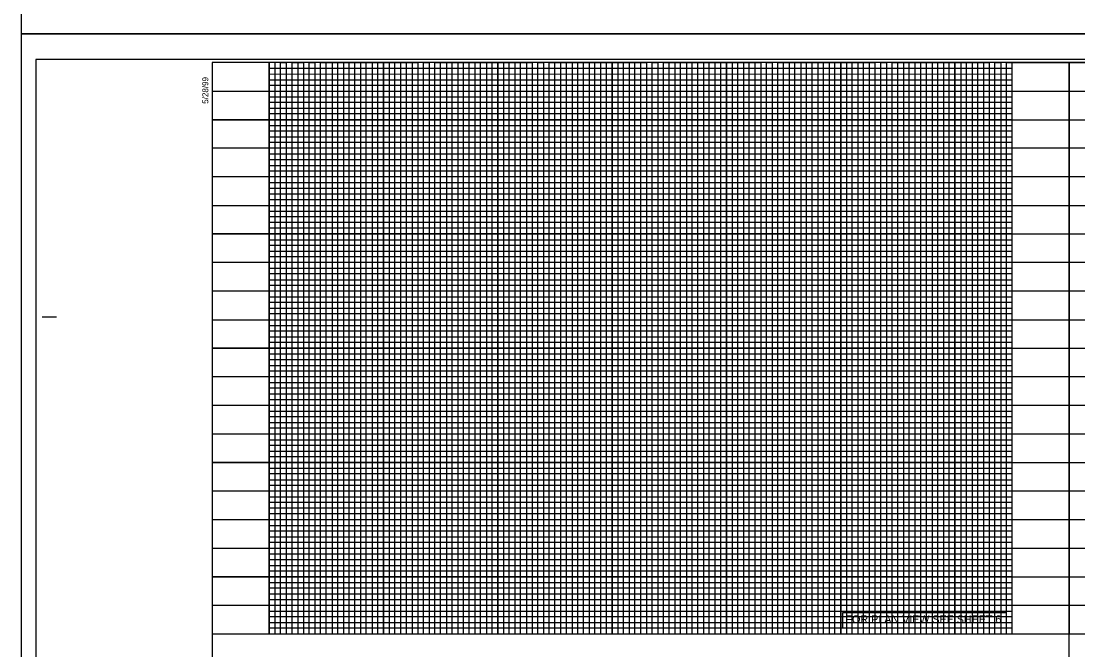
# Model space of a CAD drawing. Extents: x 1755181 to 1757273, y 729911 to 735411.
# Drawn here: x 1755181 to 1756105, y 730472 to 731022 of the extents above; entities that cross this region are included whole.
import ezdxf

# ---------------------------------------------------------------- set-up
doc = ezdxf.new("R2010")
doc.units = 0
for name, color, linetype in [('Prop Grid Mask', 7, 'Continuous'), ('Prop VPI Label', 7, 'Continuous'), ('Scratch_Level_3', 7, 'Continuous'), ('Sheet Cutting Line CELL', 7, 'Continuous'), ('Sheet DOT Grid CELL', 7, 'Continuous'), ('Sheet Plot Border Inside CELL', 7, 'Continuous'), ('Sheet Plot Border Outside CELL', 7, 'Continuous'), ('Sheet Profile CELL', 7, 'Continuous'), ('Sheet Profile Grid Major CELL', 7, 'Continuous'), ('Sheet Profile Grid Middle CELL', 7, 'Continuous'), ('Sheet Profile Grid Minor CELL', 7, 'Continuous')]:
    doc.layers.add(name, color=color, linetype=linetype)

msp = doc.modelspace()

# ---------------------------------------------------------------- linework, layer by layer
at = {"layer": 'Prop Grid Mask'}
msp.add_lwpolyline([(1755899.57, 730504.63), (1756042.57, 730504.63), (1756042.57, 730490.9), (1755899.57, 730490.9)], close=True, dxfattribs=at)
at = {"layer": 'Scratch_Level_3'}
for points in [[(1755347.67, 730460.78), (1756097.67, 730460.78), (1756097.67, 730985.78), (1755347.67, 730985.78)], [(1756097.67, 730460.78), (1756097.67, 730985.78), (1756647.63, 730985.78), (1756647.63, 730752.66), (1756847.68, 730752.66), (1756847.68, 730460.78)]]:
    msp.add_lwpolyline(points, close=True, dxfattribs=at)
at = {"layer": 'Sheet Cutting Line CELL'}
for p, q in [((1755180.67, 732110.78), (1755180.67, 731010.78)), ((1755180.67, 731010.78), (1756864.67, 731010.78)), ((1755180.67, 731010.78), (1755180.67, 729910.78))]:
    msp.add_line(p, q, dxfattribs=at)
at = {"layer": 'Sheet DOT Grid CELL'}
for p, q in [((1755397.67, 730485.78), (1755397.67, 730985.78)), ((1755447.67, 730485.78), (1755447.67, 730985.78)), ((1755497.67, 730485.78), (1755497.67, 730985.78)), ((1755547.67, 730485.78), (1755547.67, 730985.78)), ((1755597.67, 730485.78), (1755597.67, 730985.78)), ((1755647.67, 730485.78), (1755647.67, 730985.78)), ((1755697.67, 730485.78), (1755697.67, 730985.78)), ((1755747.67, 730485.78), (1755747.67, 730985.78)), ((1755797.67, 730485.78), (1755797.67, 730985.78)), ((1755847.67, 730485.78), (1755847.67, 730985.78)), ((1755897.67, 730485.78), (1755897.67, 730985.78)), ((1755947.67, 730485.78), (1755947.67, 730985.78)), ((1755997.67, 730485.78), (1755997.67, 730985.78)), ((1756047.67, 730485.78), (1756047.67, 730985.78)), ((1756097.67, 730485.78), (1756097.67, 730985.78)), ((1756047.68, 730935.78), (1755347.67, 730935.78)), ((1756047.68, 730885.78), (1755347.67, 730885.78)), ((1756047.68, 730835.78), (1755347.67, 730835.78)), ((1756047.68, 730785.78), (1755347.67, 730785.78)), ((1756047.68, 730735.78), (1755347.67, 730735.78)), ((1756047.68, 730685.78), (1755347.67, 730685.78)), ((1756047.68, 730635.78), (1755347.67, 730635.78)), ((1756047.68, 730585.78), (1755347.67, 730585.78)), ((1756047.68, 730535.78), (1755347.67, 730535.78))]:
    msp.add_line(p, q, dxfattribs=at)
at = {"layer": 'Sheet Plot Border Inside CELL'}
msp.add_lwpolyline([(1755193.67, 729933.23), (1756860.17, 729933.23), (1756860.17, 730988.33), (1755193.67, 730988.33)], close=True, dxfattribs=at)
at = {"layer": 'Sheet Plot Border Outside CELL'}
for points in [[(1755180.67, 731010.78), (1756864.67, 731010.78), (1756864.67, 732110.78), (1755180.67, 732110.78)], [(1755180.67, 729910.78), (1756864.67, 729910.78), (1756864.67, 731010.78), (1755180.67, 731010.78)]]:
    msp.add_lwpolyline(points, close=True, dxfattribs=at)
at = {"layer": 'Sheet Profile CELL'}
for p, q in [((1756097.67, 730985.78), (1756097.67, 730485.78)), ((1755199.17, 730763.28), (1755211.67, 730763.28)), ((1755347.67, 730485.78), (1756847.67, 730485.78))]:
    msp.add_line(p, q, dxfattribs=at)
msp.add_lwpolyline([(1756847.67, 730985.78), (1755347.67, 730985.78), (1755347.67, 729935.78), (1756847.67, 729935.78)], close=True, dxfattribs=at)
at = {"layer": 'Sheet Profile Grid Major CELL'}
for points in [[(1755397.67, 730985.78), (1755397.67, 730485.78), (1755447.67, 730485.78), (1755447.67, 730985.78), (1755497.67, 730985.78), (1755497.67, 730485.78), (1755547.67, 730485.78), (1755547.67, 730985.78), (1755597.67, 730985.78), (1755597.67, 730485.78), (1755647.67, 730485.78), (1755647.67, 730985.78), (1755697.67, 730985.78), (1755697.67, 730485.78), (1755747.67, 730485.78), (1755747.67, 730985.78), (1755797.67, 730985.78), (1755797.67, 730485.78), (1755847.67, 730485.78), (1755847.67, 730985.78), (1755897.67, 730985.78), (1755897.67, 730485.78), (1755947.67, 730485.78), (1755947.67, 730985.78), (1755997.67, 730985.78), (1755997.67, 730485.78), (1756047.67, 730485.78), (1756047.67, 730985.78), (1756097.67, 730985.78), (1756097.67, 730485.78), (1756147.67, 730485.78)], [(1755347.67, 730935.78), (1756647.67, 730935.78)], [(1756647.67, 730885.78), (1755347.67, 730885.78), (1755347.67, 730835.78), (1756647.67, 730835.78)], [(1756647.63, 730785.78), (1755347.67, 730785.78), (1755347.67, 730735.78), (1756847.67, 730735.78)], [(1756847.67, 730685.78), (1755347.67, 730685.78), (1755347.67, 730635.78), (1756847.67, 730635.78)], [(1756847.67, 730585.78), (1755347.67, 730585.78), (1755347.67, 730585.78), (1755347.67, 730535.78), (1756847.67, 730535.78)]]:
    msp.add_lwpolyline(points, dxfattribs=at)
at = {"layer": 'Sheet Profile Grid Middle CELL'}
for p, q in [((1755422.67, 730985.78), (1755422.67, 730485.78)), ((1755472.67, 730485.78), (1755472.67, 730985.78)), ((1755472.67, 730985.78), (1755522.67, 730985.78)), ((1755522.67, 730985.78), (1755522.67, 730485.78)), ((1755572.67, 730485.78), (1755572.67, 730985.78)), ((1755572.67, 730985.78), (1755622.67, 730985.78)), ((1755622.67, 730985.78), (1755622.67, 730485.78)), ((1755672.67, 730485.78), (1755672.67, 730985.78)), ((1755672.67, 730985.78), (1755722.67, 730985.78)), ((1755722.67, 730985.78), (1755722.67, 730485.78)), ((1755772.67, 730485.78), (1755772.67, 730985.78)), ((1755772.67, 730985.78), (1755822.67, 730985.78)), ((1755822.67, 730985.78), (1755822.67, 730485.78)), ((1755872.67, 730485.78), (1755872.67, 730985.78)), ((1755872.67, 730985.78), (1755922.67, 730985.78)), ((1755922.67, 730985.78), (1755922.67, 730485.78)), ((1755972.67, 730485.78), (1755972.67, 730985.78)), ((1755972.67, 730985.78), (1756022.67, 730985.78)), ((1756022.67, 730985.78), (1756022.67, 730485.78)), ((1756072.67, 730985.78), (1756122.67, 730985.78)), ((1755347.67, 730960.78), (1756647.62, 730960.78)), ((1755422.67, 730485.78), (1755472.67, 730485.78)), ((1755522.67, 730485.78), (1755572.67, 730485.78)), ((1755622.67, 730485.78), (1755672.67, 730485.78)), ((1755722.67, 730485.78), (1755772.67, 730485.78)), ((1755822.67, 730485.78), (1755872.67, 730485.78)), ((1755922.67, 730485.78), (1755972.67, 730485.78)), ((1755972.67, 730485.78), (1755972.67, 730485.78)), ((1756022.67, 730485.78), (1756072.67, 730485.78))]:
    msp.add_line(p, q, dxfattribs=at)
for points in [[(1756647.67, 730910.78), (1755347.67, 730910.78), (1755347.67, 730860.78), (1756647.67, 730860.78)], [(1756647.62, 730810.78), (1755347.67, 730810.78), (1755347.67, 730760.78), (1756647.63, 730760.78)], [(1756847.67, 730710.78), (1755347.67, 730710.78), (1755347.67, 730660.78), (1756847.67, 730660.78)], [(1756847.67, 730610.78), (1755347.67, 730610.78), (1755347.67, 730560.78), (1756847.67, 730560.78)], [(1756847.67, 730510.78), (1755347.67, 730510.78)]]:
    msp.add_lwpolyline(points, dxfattribs=at)
at = {"layer": 'Sheet Profile Grid Minor CELL'}
for p, q in [((1755927.67, 730985.78), (1755927.67, 730485.78)), ((1755932.67, 730485.78), (1755932.67, 730985.78)), ((1755932.67, 730985.78), (1755937.67, 730985.78)), ((1755937.67, 730985.78), (1755937.67, 730485.78)), ((1755942.67, 730485.78), (1755942.67, 730985.78)), ((1755942.67, 730985.78), (1755952.67, 730985.78)), ((1755952.67, 730985.78), (1755952.67, 730485.78)), ((1755957.67, 730485.78), (1755957.67, 730985.78)), ((1755957.67, 730985.78), (1755962.67, 730985.78)), ((1755962.67, 730985.78), (1755962.67, 730485.78)), ((1755967.67, 730485.78), (1755967.67, 730985.78)), ((1755967.67, 730985.78), (1755977.67, 730985.78)), ((1755977.67, 730985.78), (1755977.67, 730485.78)), ((1755982.67, 730485.78), (1755982.67, 730985.78)), ((1755982.67, 730985.78), (1755987.67, 730985.78)), ((1755987.67, 730985.78), (1755987.67, 730485.78)), ((1755992.67, 730485.78), (1755992.67, 730985.78)), ((1755992.67, 730985.78), (1756002.67, 730985.78)), ((1756002.67, 730985.78), (1756002.67, 730485.78)), ((1756007.67, 730485.78), (1756007.67, 730985.78)), ((1756007.67, 730985.78), (1756012.67, 730985.78)), ((1756012.67, 730985.78), (1756012.67, 730485.78)), ((1756017.67, 730485.78), (1756017.67, 730985.78)), ((1756017.67, 730985.78), (1756027.67, 730985.78)), ((1756027.67, 730985.78), (1756027.67, 730485.78)), ((1756032.67, 730485.78), (1756032.67, 730985.78)), ((1756032.67, 730985.78), (1756037.67, 730985.78)), ((1756037.67, 730985.78), (1756037.67, 730485.78)), ((1756042.67, 730485.78), (1756042.67, 730985.78)), ((1756042.67, 730985.78), (1756052.67, 730985.78)), ((1756057.67, 730985.78), (1756062.67, 730985.78)), ((1756067.67, 730985.78), (1756077.67, 730985.78)), ((1756082.67, 730985.78), (1756087.67, 730985.78)), ((1756092.67, 730985.78), (1756102.67, 730985.78)), ((1755397.67, 730980.78), (1756047.68, 730980.78)), ((1755397.67, 730975.78), (1755397.67, 730975.78)), ((1756047.68, 730975.62), (1755397.67, 730975.43)), ((1755397.67, 730970.78), (1756047.68, 730970.78)), ((1756047.68, 730850.78), (1755397.67, 730850.78)), ((1756047.68, 730845.78), (1755397.67, 730845.78)), ((1756047.68, 730840.78), (1755397.67, 730840.78)), ((1755397.67, 730830.78), (1756047.68, 730830.78)), ((1756047.68, 730825.78), (1755397.67, 730825.78)), ((1755397.67, 730820.78), (1756047.68, 730820.78)), ((1756047.68, 730800.78), (1755397.67, 730800.78)), ((1755397.67, 730795.78), (1756047.68, 730795.78)), ((1756047.68, 730775.78), (1755397.67, 730775.78)), ((1755397.67, 730770.78), (1756047.68, 730770.78)), ((1756047.68, 730750.78), (1755397.67, 730750.78)), ((1755397.67, 730745.78), (1756047.68, 730745.78)), ((1756047.68, 730740.78), (1755397.67, 730740.78)), ((1755397.67, 730730.78), (1756047.68, 730730.78)), ((1756047.68, 730725.78), (1755397.67, 730725.78)), ((1755397.67, 730720.78), (1756047.68, 730720.78)), ((1756047.68, 730715.78), (1755397.67, 730715.78)), ((1755397.67, 730705.78), (1756047.68, 730705.78)), ((1756047.68, 730700.78), (1755397.67, 730700.78)), ((1755397.67, 730695.78), (1756047.68, 730695.78)), ((1756047.68, 730690.78), (1755397.67, 730690.78)), ((1755397.67, 730680.78), (1756047.68, 730680.78)), ((1756047.68, 730675.78), (1755397.67, 730675.78)), ((1755397.67, 730670.78), (1756047.68, 730670.78)), ((1756047.68, 730665.78), (1755397.67, 730665.78)), ((1755397.67, 730655.78), (1756047.68, 730655.78)), ((1756047.68, 730650.78), (1755397.67, 730650.78)), ((1755397.67, 730645.78), (1756047.68, 730645.78)), ((1756047.68, 730640.78), (1755397.67, 730640.78)), ((1755397.67, 730630.78), (1756047.68, 730630.78)), ((1756047.68, 730625.78), (1755397.67, 730625.78)), ((1755397.67, 730620.78), (1756047.68, 730620.78)), ((1756047.68, 730615.78), (1755397.67, 730615.78)), ((1755397.67, 730605.78), (1756047.68, 730605.78)), ((1756047.68, 730600.78), (1755397.67, 730600.78)), ((1756047.68, 730595.78), (1755397.67, 730595.78)), ((1756047.68, 730590.78), (1755397.67, 730590.78)), ((1755397.67, 730580.78), (1756047.68, 730580.78)), ((1756047.68, 730575.78), (1755397.67, 730575.78)), ((1755397.67, 730570.78), (1756047.68, 730570.78)), ((1756047.68, 730565.78), (1755397.67, 730565.78)), ((1755397.67, 730555.78), (1756047.68, 730555.78)), ((1756047.68, 730550.78), (1755397.67, 730550.78)), ((1755397.67, 730545.78), (1756047.68, 730545.78)), ((1756047.68, 730540.78), (1755397.67, 730540.78)), ((1755397.67, 730530.78), (1756047.68, 730530.78)), ((1756047.68, 730525.78), (1755397.67, 730525.78)), ((1755397.67, 730520.78), (1756047.68, 730520.78)), ((1756047.68, 730515.78), (1755397.67, 730515.78)), ((1755397.67, 730505.78), (1756047.68, 730505.78)), ((1756047.68, 730500.78), (1755397.67, 730500.78)), ((1755397.67, 730495.78), (1756047.68, 730495.78)), ((1755927.67, 730485.78), (1755932.67, 730485.78)), ((1755937.67, 730485.78), (1755942.67, 730485.78)), ((1755952.67, 730485.78), (1755957.67, 730485.78)), ((1755962.67, 730485.78), (1755967.67, 730485.78)), ((1755977.67, 730485.78), (1755982.67, 730485.78)), ((1755987.67, 730485.78), (1755992.67, 730485.78)), ((1756002.67, 730485.78), (1756007.67, 730485.78)), ((1756012.67, 730485.78), (1756017.67, 730485.78)), ((1756027.67, 730485.78), (1756032.67, 730485.78)), ((1756037.67, 730485.78), (1756042.67, 730485.78)), ((1756052.67, 730485.78), (1756052.67, 730485.78)), ((1756052.67, 730485.78), (1756057.67, 730485.78))]:
    msp.add_line(p, q, dxfattribs=at)
for points in [[(1755402.67, 730985.78), (1755402.67, 730485.78), (1755407.67, 730485.78), (1755407.67, 730985.78), (1755412.67, 730985.78), (1755412.67, 730485.78), (1755417.67, 730485.78), (1755417.67, 730985.78), (1755427.67, 730985.78), (1755427.67, 730485.78), (1755432.67, 730485.78), (1755432.67, 730985.78), (1755437.67, 730985.78), (1755437.67, 730485.78), (1755442.67, 730485.78), (1755452.67, 730485.78), (1755457.67, 730485.78), (1755457.67, 730985.78), (1755462.67, 730985.78), (1755462.67, 730485.78), (1755467.67, 730485.78), (1755467.67, 730985.78), (1755477.67, 730985.78), (1755477.67, 730485.78), (1755482.67, 730485.78), (1755482.67, 730985.78), (1755487.67, 730985.78), (1755487.67, 730485.78), (1755492.67, 730485.78), (1755492.67, 730985.78), (1755502.67, 730985.78), (1755502.67, 730485.78), (1755507.67, 730485.78), (1755507.67, 730985.78), (1755512.67, 730985.78), (1755512.67, 730485.78), (1755517.67, 730485.78), (1755517.67, 730985.78), (1755527.67, 730985.78), (1755527.67, 730485.78), (1755532.67, 730485.78), (1755532.67, 730985.78), (1755537.67, 730985.78), (1755537.67, 730485.78), (1755542.67, 730485.78), (1755542.67, 730985.78), (1755552.67, 730985.78), (1755552.67, 730485.78), (1755557.67, 730485.78), (1755557.67, 730985.78), (1755562.67, 730985.78), (1755562.67, 730485.78), (1755567.67, 730485.78), (1755567.67, 730985.78), (1755577.67, 730985.78), (1755577.67, 730485.78), (1755582.67, 730485.78), (1755582.67, 730985.78), (1755587.67, 730985.78), (1755587.67, 730485.78), (1755592.67, 730485.78), (1755592.67, 730985.78), (1755602.67, 730985.78), (1755602.67, 730485.78), (1755607.67, 730485.78), (1755607.67, 730985.78), (1755612.67, 730985.78), (1755612.67, 730485.78)], [(1755442.67, 730485.78), (1755442.67, 730985.78), (1755452.67, 730985.78), (1755452.67, 730485.78)], [(1755612.67, 730485.78), (1755617.67, 730485.78), (1755617.67, 730985.78), (1755627.67, 730985.78), (1755627.67, 730485.78), (1755632.67, 730485.78), (1755632.67, 730985.78), (1755637.67, 730985.78), (1755637.67, 730485.78), (1755642.67, 730485.78), (1755642.67, 730985.78), (1755652.67, 730985.78), (1755652.67, 730485.78), (1755657.67, 730485.78), (1755657.67, 730985.78), (1755662.67, 730985.78), (1755662.67, 730485.78), (1755667.67, 730485.78), (1755667.67, 730985.78), (1755677.67, 730985.78), (1755677.67, 730485.78), (1755682.67, 730485.78), (1755682.67, 730985.78), (1755687.67, 730985.78), (1755687.67, 730485.78), (1755692.67, 730485.78), (1755692.67, 730985.78), (1755702.67, 730985.78), (1755702.67, 730485.78), (1755707.67, 730485.78), (1755707.67, 730985.78), (1755712.67, 730985.78), (1755712.67, 730485.78), (1755717.67, 730485.78), (1755717.67, 730985.78), (1755727.67, 730985.78), (1755727.67, 730485.78), (1755732.67, 730485.78), (1755732.67, 730985.78), (1755737.67, 730985.78), (1755737.67, 730485.78), (1755742.67, 730485.78), (1755742.67, 730985.78), (1755752.67, 730985.78), (1755752.67, 730485.78), (1755757.67, 730485.78), (1755757.67, 730985.78), (1755762.67, 730985.78), (1755762.67, 730485.78), (1755767.67, 730485.78), (1755767.67, 730985.78), (1755777.67, 730985.78), (1755777.67, 730485.78), (1755782.67, 730485.78), (1755782.67, 730985.78), (1755787.67, 730985.78), (1755787.67, 730485.78), (1755792.67, 730485.78), (1755792.67, 730985.78), (1755802.67, 730985.78), (1755802.67, 730485.78), (1755807.67, 730485.78), (1755807.67, 730985.78), (1755812.67, 730985.78), (1755812.67, 730485.78), (1755817.67, 730485.78), (1755817.67, 730985.78), (1755827.67, 730985.78), (1755827.67, 730485.78), (1755832.67, 730485.78), (1755832.67, 730985.78), (1755837.67, 730985.78), (1755837.67, 730485.78), (1755842.67, 730485.78), (1755842.67, 730985.78), (1755852.67, 730985.78), (1755852.67, 730485.78), (1755857.67, 730485.78), (1755857.67, 730985.78), (1755862.67, 730985.78), (1755862.67, 730485.78), (1755867.67, 730485.78), (1755867.67, 730985.78), (1755877.67, 730985.78), (1755877.67, 730485.78), (1755882.67, 730485.78), (1755882.67, 730985.78), (1755887.67, 730985.78), (1755887.67, 730485.78), (1755892.67, 730485.78), (1755892.67, 730985.78), (1755902.67, 730985.78), (1755902.67, 730485.78), (1755907.67, 730485.78), (1755907.67, 730985.78), (1755912.67, 730985.78), (1755912.67, 730485.78), (1755917.67, 730485.78), (1755917.67, 730985.78), (1755927.67, 730985.78)], [(1756047.68, 730965.78), (1755397.67, 730965.78), (1755397.67, 730955.78), (1756047.68, 730955.78)], [(1756047.68, 730950.78), (1755397.67, 730950.78), (1755397.67, 730945.78), (1756047.68, 730945.78)], [(1756047.68, 730940.78), (1755397.67, 730940.78), (1755397.67, 730930.78), (1756047.68, 730930.78)], [(1756047.68, 730925.78), (1755397.67, 730925.78), (1755397.67, 730920.78), (1756047.68, 730920.78)], [(1756047.68, 730915.78), (1755397.67, 730915.78), (1755397.67, 730905.78), (1756047.68, 730905.78)], [(1756047.68, 730900.78), (1755397.67, 730900.78), (1755397.67, 730895.78), (1756047.68, 730895.78)], [(1756047.68, 730890.78), (1755397.67, 730890.78), (1755397.67, 730880.78), (1756047.68, 730880.78)], [(1756047.68, 730875.68), (1755397.77, 730875.68), (1755397.77, 730870.78), (1756047.68, 730870.78)], [(1756047.68, 730865.78), (1755397.67, 730865.78), (1755397.67, 730855.78), (1756047.68, 730855.78)], [(1756047.68, 730815.78), (1755397.67, 730815.78), (1755397.67, 730805.78), (1756047.68, 730805.78)], [(1756047.68, 730790.78), (1755397.67, 730790.78), (1755397.67, 730780.78), (1756047.68, 730780.78)], [(1756047.68, 730765.78), (1755397.67, 730765.78), (1755397.67, 730755.78), (1756047.68, 730755.78)], [(1756047.68, 730490.78), (1755397.67, 730490.78)]]:
    msp.add_lwpolyline(points, dxfattribs=at)

# ---------------------------------------------------------------- texts
at = {"layer": 'Prop VPI Label'}
msp.add_text('FOR PLAN VIEW SEE SHEET 6', height=7, dxfattribs=at).set_placement((1755901.97, 730495.14))
at = {"layer": 'Sheet Profile CELL'}
msp.add_text('5/28/99', height=5.25, rotation=90, dxfattribs=at).set_placement((1755344.43, 730949.7))

doc.saveas('drawing.dxf')
